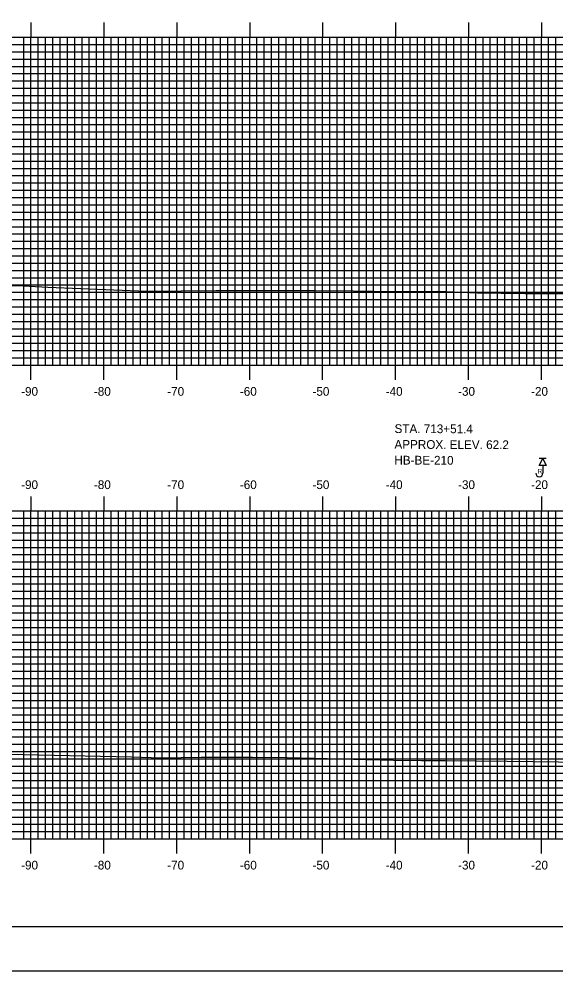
# Model space of a CAD drawing. Extents: x 855690 to 856034, y 364366 to 364586.
# Drawn here: x 855764.6 to 855838.3, y 364365.7 to 364496.3 of the extents above; entities that cross this region are included whole.
import ezdxf

# ---------------------------------------------------------------- set-up
doc = ezdxf.new("R2010")
doc.units = 0
for name, color, linetype in [('BORDER', 7, 'Continuous'), ('BORING - REFUSAL', 7, 'Continuous'), ('H_V ANNOTATION', 7, 'Continuous'), ('MAJOR', 7, 'Continuous'), ('MINOR', 7, 'Continuous'), ('PLOT BOUNDARY', 7, 'Continuous'), ('S_Roadway_Centerline', 7, 'Continuous')]:
    doc.layers.add(name, color=color, linetype=linetype)

msp = doc.modelspace()

# ---------------------------------------------------------------- linework, layer by layer
at = {"layer": 'BORDER'}
msp.add_lwpolyline([(855706.68, 364371.79), (856026.68, 364371.79), (856026.68, 364581.79), (855706.68, 364581.79)], close=True, dxfattribs=at)
at = {"layer": 'BORING - REFUSAL'}
for p, q in [((855836.96, 364435.99), (855836, 364435.99)), ((855836.48, 364435.03), (855836.48, 364433.97))]:
    msp.add_line(p, q, dxfattribs=at)
msp.add_lwpolyline([(855836.48, 364435.99), (855836.96, 364435.03), (855836, 364435.03)], close=True, dxfattribs=at)
msp.add_arc((855836, 364433.97), 0.485, 180, 0, dxfattribs=at)
at = {"layer": 'MAJOR'}
for p, q in [((855766.28, 364495.79), (855766.28, 364493.79)), ((855776.28, 364495.79), (855776.28, 364493.79)), ((855786.28, 364495.79), (855786.28, 364493.79)), ((855796.28, 364495.79), (855796.28, 364493.79)), ((855806.28, 364495.79), (855806.28, 364493.79)), ((855816.28, 364495.79), (855816.28, 364493.79)), ((855826.28, 364495.79), (855826.28, 364493.79)), ((855836.28, 364495.79), (855836.28, 364493.79)), ((855716.28, 364493.79), (855996.28, 364493.79)), ((855716.28, 364493.79), (855996.28, 364493.79)), ((855766.28, 364448.79), (855766.28, 364493.79)), ((855776.28, 364448.79), (855776.28, 364493.79)), ((855786.28, 364448.79), (855786.28, 364493.79)), ((855796.28, 364448.79), (855796.28, 364493.79)), ((855806.28, 364448.79), (855806.28, 364493.79)), ((855816.28, 364448.79), (855816.28, 364493.79)), ((855826.28, 364448.79), (855826.28, 364493.79)), ((855836.28, 364448.79), (855836.28, 364493.79)), ((855716.28, 364488.79), (855996.28, 364488.79)), ((855716.28, 364483.79), (855996.28, 364483.79)), ((855716.28, 364478.79), (855996.28, 364478.79)), ((855716.28, 364473.79), (855996.28, 364473.79)), ((855716.28, 364468.79), (855996.28, 364468.79)), ((855716.28, 364463.79), (855996.28, 364463.79)), ((855716.28, 364458.79), (855996.28, 364458.79)), ((855716.28, 364453.79), (855996.28, 364453.79)), ((855716.28, 364448.79), (855996.28, 364448.79)), ((855716.28, 364448.79), (855996.28, 364448.79)), ((855766.28, 364446.78), (855766.28, 364448.79)), ((855776.28, 364446.78), (855776.28, 364448.79)), ((855786.28, 364446.78), (855786.28, 364448.79)), ((855796.28, 364446.78), (855796.28, 364448.79)), ((855806.28, 364446.78), (855806.28, 364448.79)), ((855816.28, 364446.78), (855816.28, 364448.79)), ((855826.28, 364446.78), (855826.28, 364448.79)), ((855836.28, 364446.78), (855836.28, 364448.79)), ((855766.28, 364430.79), (855766.28, 364428.79)), ((855776.28, 364430.79), (855776.28, 364428.79)), ((855786.28, 364430.79), (855786.28, 364428.79)), ((855796.28, 364430.79), (855796.28, 364428.79)), ((855806.28, 364430.79), (855806.28, 364428.79)), ((855816.28, 364430.79), (855816.28, 364428.79)), ((855826.28, 364430.79), (855826.28, 364428.79)), ((855836.28, 364430.79), (855836.28, 364428.79)), ((855716.28, 364428.79), (855996.28, 364428.79)), ((855716.28, 364428.79), (855996.28, 364428.79)), ((855766.28, 364383.79), (855766.28, 364428.79)), ((855776.28, 364383.79), (855776.28, 364428.79)), ((855786.28, 364383.79), (855786.28, 364428.79)), ((855796.28, 364383.79), (855796.28, 364428.79)), ((855806.28, 364383.79), (855806.28, 364428.79)), ((855816.28, 364383.79), (855816.28, 364428.79)), ((855826.28, 364383.79), (855826.28, 364428.79)), ((855836.28, 364383.79), (855836.28, 364428.79)), ((855716.28, 364423.79), (855996.28, 364423.79)), ((855716.28, 364418.79), (855996.28, 364418.79)), ((855716.28, 364413.79), (855996.28, 364413.79)), ((855716.28, 364408.79), (855996.28, 364408.79)), ((855716.28, 364403.79), (855996.28, 364403.79)), ((855716.28, 364398.79), (855996.28, 364398.79)), ((855716.28, 364393.79), (855996.28, 364393.79)), ((855716.28, 364388.79), (855996.28, 364388.79)), ((855716.28, 364383.79), (855996.28, 364383.79)), ((855716.28, 364383.79), (855996.28, 364383.79)), ((855766.28, 364381.78), (855766.28, 364383.79)), ((855776.28, 364381.78), (855776.28, 364383.79)), ((855786.28, 364381.78), (855786.28, 364383.79)), ((855796.28, 364381.78), (855796.28, 364383.79)), ((855806.28, 364381.78), (855806.28, 364383.79)), ((855816.28, 364381.78), (855816.28, 364383.79)), ((855826.28, 364381.78), (855826.28, 364383.79)), ((855836.28, 364381.78), (855836.28, 364383.79))]:
    msp.add_line(p, q, dxfattribs=at)
at = {"layer": 'MINOR'}
for p, q in [((855765.28, 364448.79), (855765.28, 364493.79)), ((855767.28, 364448.79), (855767.28, 364493.79)), ((855768.28, 364448.79), (855768.28, 364493.79)), ((855769.28, 364448.79), (855769.28, 364493.79)), ((855770.28, 364448.79), (855770.28, 364493.79)), ((855771.28, 364448.79), (855771.28, 364493.79)), ((855772.28, 364448.79), (855772.28, 364493.79)), ((855773.28, 364448.79), (855773.28, 364493.79)), ((855774.28, 364448.79), (855774.28, 364493.79)), ((855775.28, 364448.79), (855775.28, 364493.79)), ((855777.28, 364448.79), (855777.28, 364493.79)), ((855778.28, 364448.79), (855778.28, 364493.79)), ((855779.28, 364448.79), (855779.28, 364493.79)), ((855780.28, 364448.79), (855780.28, 364493.79)), ((855781.28, 364448.79), (855781.28, 364493.79)), ((855782.28, 364448.79), (855782.28, 364493.79)), ((855783.28, 364448.79), (855783.28, 364493.79)), ((855784.28, 364448.79), (855784.28, 364493.79)), ((855785.28, 364448.79), (855785.28, 364493.79)), ((855787.28, 364448.79), (855787.28, 364493.79)), ((855788.28, 364448.79), (855788.28, 364493.79)), ((855789.28, 364448.79), (855789.28, 364493.79)), ((855790.28, 364448.79), (855790.28, 364493.79)), ((855791.28, 364448.79), (855791.28, 364493.79)), ((855792.28, 364448.79), (855792.28, 364493.79)), ((855793.28, 364448.79), (855793.28, 364493.79)), ((855794.28, 364448.79), (855794.28, 364493.79)), ((855795.28, 364448.79), (855795.28, 364493.79)), ((855797.28, 364448.79), (855797.28, 364493.79)), ((855798.28, 364448.79), (855798.28, 364493.79)), ((855799.28, 364448.79), (855799.28, 364493.79)), ((855800.28, 364448.79), (855800.28, 364493.79)), ((855801.28, 364448.79), (855801.28, 364493.79)), ((855802.28, 364448.79), (855802.28, 364493.79)), ((855803.28, 364448.79), (855803.28, 364493.79)), ((855804.28, 364448.79), (855804.28, 364493.79)), ((855805.28, 364448.79), (855805.28, 364493.79)), ((855807.28, 364448.79), (855807.28, 364493.79)), ((855808.28, 364448.79), (855808.28, 364493.79)), ((855809.28, 364448.79), (855809.28, 364493.79)), ((855810.28, 364448.79), (855810.28, 364493.79)), ((855811.28, 364448.79), (855811.28, 364493.79)), ((855812.28, 364448.79), (855812.28, 364493.79)), ((855813.28, 364448.79), (855813.28, 364493.79)), ((855814.28, 364448.79), (855814.28, 364493.79)), ((855815.28, 364448.79), (855815.28, 364493.79)), ((855817.28, 364448.79), (855817.28, 364493.79)), ((855818.28, 364448.79), (855818.28, 364493.79)), ((855819.28, 364448.79), (855819.28, 364493.79)), ((855820.28, 364448.79), (855820.28, 364493.79)), ((855821.28, 364448.79), (855821.28, 364493.79)), ((855822.28, 364448.79), (855822.28, 364493.79)), ((855823.28, 364448.79), (855823.28, 364493.79)), ((855824.28, 364448.79), (855824.28, 364493.79)), ((855825.28, 364448.79), (855825.28, 364493.79)), ((855827.28, 364448.79), (855827.28, 364493.79)), ((855828.28, 364448.79), (855828.28, 364493.79)), ((855829.28, 364448.79), (855829.28, 364493.79)), ((855830.28, 364448.79), (855830.28, 364493.79)), ((855831.28, 364448.79), (855831.28, 364493.79)), ((855832.28, 364448.79), (855832.28, 364493.79)), ((855833.28, 364448.79), (855833.28, 364493.79)), ((855834.28, 364448.79), (855834.28, 364493.79)), ((855835.28, 364448.79), (855835.28, 364493.79)), ((855837.28, 364448.79), (855837.28, 364493.79)), ((855838.28, 364448.79), (855838.28, 364493.79)), ((855716.28, 364492.79), (855996.28, 364492.79)), ((855716.28, 364491.79), (855996.28, 364491.79)), ((855716.28, 364490.79), (855996.28, 364490.79)), ((855716.28, 364489.79), (855996.28, 364489.79)), ((855716.28, 364487.79), (855996.28, 364487.79)), ((855716.28, 364486.79), (855996.28, 364486.79)), ((855716.28, 364485.79), (855996.28, 364485.79)), ((855716.28, 364484.79), (855996.28, 364484.79)), ((855716.28, 364482.79), (855996.28, 364482.79)), ((855716.28, 364481.79), (855996.28, 364481.79)), ((855716.28, 364480.79), (855996.28, 364480.79)), ((855716.28, 364479.79), (855996.28, 364479.79)), ((855716.28, 364477.79), (855996.28, 364477.79)), ((855716.28, 364476.79), (855996.28, 364476.79)), ((855716.28, 364475.79), (855996.28, 364475.79)), ((855716.28, 364474.79), (855996.28, 364474.79)), ((855716.28, 364472.79), (855996.28, 364472.79)), ((855716.28, 364471.79), (855996.28, 364471.79)), ((855716.28, 364470.79), (855996.28, 364470.79)), ((855716.28, 364469.79), (855996.28, 364469.79)), ((855716.28, 364467.79), (855996.28, 364467.79)), ((855716.28, 364466.79), (855996.28, 364466.79)), ((855716.28, 364465.79), (855996.28, 364465.79)), ((855716.28, 364464.79), (855996.28, 364464.79)), ((855716.28, 364462.79), (855996.28, 364462.79)), ((855716.28, 364461.79), (855996.28, 364461.79)), ((855716.28, 364460.79), (855996.28, 364460.79)), ((855716.28, 364459.79), (855996.28, 364459.79)), ((855716.28, 364457.79), (855996.28, 364457.79)), ((855716.28, 364456.79), (855996.28, 364456.79)), ((855716.28, 364455.79), (855996.28, 364455.79)), ((855716.28, 364454.79), (855996.28, 364454.79)), ((855716.28, 364452.79), (855996.28, 364452.79)), ((855716.28, 364451.79), (855996.28, 364451.79)), ((855716.28, 364450.79), (855996.28, 364450.79)), ((855716.28, 364449.79), (855996.28, 364449.79)), ((855716.28, 364427.79), (855996.28, 364427.79)), ((855765.28, 364383.79), (855765.28, 364428.79)), ((855767.28, 364383.79), (855767.28, 364428.79)), ((855768.28, 364383.79), (855768.28, 364428.79)), ((855769.28, 364383.79), (855769.28, 364428.79)), ((855770.28, 364383.79), (855770.28, 364428.79)), ((855771.28, 364383.79), (855771.28, 364428.79)), ((855772.28, 364383.79), (855772.28, 364428.79)), ((855773.28, 364383.79), (855773.28, 364428.79)), ((855774.28, 364383.79), (855774.28, 364428.79)), ((855775.28, 364383.79), (855775.28, 364428.79)), ((855777.28, 364383.79), (855777.28, 364428.79)), ((855778.28, 364383.79), (855778.28, 364428.79)), ((855779.28, 364383.79), (855779.28, 364428.79)), ((855780.28, 364383.79), (855780.28, 364428.79)), ((855781.28, 364383.79), (855781.28, 364428.79)), ((855782.28, 364383.79), (855782.28, 364428.79)), ((855783.28, 364383.79), (855783.28, 364428.79)), ((855784.28, 364383.79), (855784.28, 364428.79)), ((855785.28, 364383.79), (855785.28, 364428.79)), ((855787.28, 364383.79), (855787.28, 364428.79)), ((855788.28, 364383.79), (855788.28, 364428.79)), ((855789.28, 364383.79), (855789.28, 364428.79)), ((855790.28, 364383.79), (855790.28, 364428.79)), ((855791.28, 364383.79), (855791.28, 364428.79)), ((855792.28, 364383.79), (855792.28, 364428.79)), ((855793.28, 364383.79), (855793.28, 364428.79)), ((855794.28, 364383.79), (855794.28, 364428.79)), ((855795.28, 364383.79), (855795.28, 364428.79)), ((855797.28, 364383.79), (855797.28, 364428.79)), ((855798.28, 364383.79), (855798.28, 364428.79)), ((855799.28, 364383.79), (855799.28, 364428.79)), ((855800.28, 364383.79), (855800.28, 364428.79)), ((855801.28, 364383.79), (855801.28, 364428.79)), ((855802.28, 364383.79), (855802.28, 364428.79)), ((855803.28, 364383.79), (855803.28, 364428.79)), ((855804.28, 364383.79), (855804.28, 364428.79)), ((855805.28, 364383.79), (855805.28, 364428.79)), ((855807.28, 364383.79), (855807.28, 364428.79)), ((855808.28, 364383.79), (855808.28, 364428.79)), ((855809.28, 364383.79), (855809.28, 364428.79)), ((855810.28, 364383.79), (855810.28, 364428.79)), ((855811.28, 364383.79), (855811.28, 364428.79)), ((855812.28, 364383.79), (855812.28, 364428.79)), ((855813.28, 364383.79), (855813.28, 364428.79)), ((855814.28, 364383.79), (855814.28, 364428.79)), ((855815.28, 364383.79), (855815.28, 364428.79)), ((855817.28, 364383.79), (855817.28, 364428.79)), ((855818.28, 364383.79), (855818.28, 364428.79)), ((855819.28, 364383.79), (855819.28, 364428.79)), ((855820.28, 364383.79), (855820.28, 364428.79)), ((855821.28, 364383.79), (855821.28, 364428.79)), ((855822.28, 364383.79), (855822.28, 364428.79)), ((855823.28, 364383.79), (855823.28, 364428.79)), ((855824.28, 364383.79), (855824.28, 364428.79)), ((855825.28, 364383.79), (855825.28, 364428.79)), ((855827.28, 364383.79), (855827.28, 364428.79)), ((855828.28, 364383.79), (855828.28, 364428.79)), ((855829.28, 364383.79), (855829.28, 364428.79)), ((855830.28, 364383.79), (855830.28, 364428.79)), ((855831.28, 364383.79), (855831.28, 364428.79)), ((855832.28, 364383.79), (855832.28, 364428.79)), ((855833.28, 364383.79), (855833.28, 364428.79)), ((855834.28, 364383.79), (855834.28, 364428.79)), ((855835.28, 364383.79), (855835.28, 364428.79)), ((855837.28, 364383.79), (855837.28, 364428.79)), ((855838.28, 364383.79), (855838.28, 364428.79)), ((855716.28, 364426.79), (855996.28, 364426.79)), ((855716.28, 364425.79), (855996.28, 364425.79)), ((855716.28, 364424.79), (855996.28, 364424.79)), ((855716.28, 364422.79), (855996.28, 364422.79)), ((855716.28, 364421.79), (855996.28, 364421.79)), ((855716.28, 364420.79), (855996.28, 364420.79)), ((855716.28, 364419.79), (855996.28, 364419.79)), ((855716.28, 364417.79), (855996.28, 364417.79)), ((855716.28, 364416.79), (855996.28, 364416.79)), ((855716.28, 364415.79), (855996.28, 364415.79)), ((855716.28, 364414.79), (855996.28, 364414.79)), ((855716.28, 364412.79), (855996.28, 364412.79)), ((855716.28, 364411.79), (855996.28, 364411.79)), ((855716.28, 364410.79), (855996.28, 364410.79)), ((855716.28, 364409.79), (855996.28, 364409.79)), ((855716.28, 364407.79), (855996.28, 364407.79)), ((855716.28, 364406.79), (855996.28, 364406.79)), ((855716.28, 364405.79), (855996.28, 364405.79)), ((855716.28, 364404.79), (855996.28, 364404.79)), ((855716.28, 364402.79), (855996.28, 364402.79)), ((855716.28, 364401.79), (855996.28, 364401.79)), ((855716.28, 364400.79), (855996.28, 364400.79)), ((855716.28, 364399.79), (855996.28, 364399.79)), ((855716.28, 364397.79), (855996.28, 364397.79)), ((855716.28, 364396.79), (855996.28, 364396.79)), ((855716.28, 364395.79), (855996.28, 364395.79)), ((855716.28, 364394.79), (855996.28, 364394.79)), ((855716.28, 364392.79), (855996.28, 364392.79)), ((855716.28, 364391.79), (855996.28, 364391.79)), ((855716.28, 364390.79), (855996.28, 364390.79)), ((855716.28, 364389.79), (855996.28, 364389.79)), ((855716.28, 364387.79), (855996.28, 364387.79)), ((855716.28, 364386.79), (855996.28, 364386.79)), ((855716.28, 364385.79), (855996.28, 364385.79)), ((855716.28, 364384.79), (855996.28, 364384.79))]:
    msp.add_line(p, q, dxfattribs=at)
at = {"layer": 'PLOT BOUNDARY'}
msp.add_lwpolyline([(855690.5, 364365.67), (856030.5, 364365.67), (856030.5, 364585.67), (855690.5, 364585.67)], close=True, dxfattribs=at)
at = {"layer": 'S_Roadway_Centerline'}
for points in [[(855716.28, 364459.71), (855721.54, 364459.71), (855736.38, 364459.78), (855740.54, 364459.68), (855745.4, 364459.58), (855764.38, 364459.71), (855768.57, 364459.49), (855782.16, 364458.94), (855786.89, 364459), (855791.64, 364459.04), (855805.12, 364459.05), (855810.51, 364459), (855816.17, 364458.91), (855822.08, 364458.96), (855827.51, 364458.73), (855834.03, 364458.61), (855840.8, 364458.61)], [(855716.28, 364396.58), (855718.3, 364396.5), (855737.2, 364395.84), (855738.26, 364395.83), (855743.8, 364395.75), (855760.2, 364395.47), (855763.11, 364395.42), (855780.07, 364395.03), (855784.13, 364394.9), (855789.62, 364395.01), (855796.66, 364395.01), (855801.4, 364394.98), (855815.99, 364394.6), (855819.85, 364394.55), (855823.07, 364394.55), (855831.57, 364394.47), (855842.14, 364394.32)]]:
    msp.add_lwpolyline(points, dxfattribs=at)

# ---------------------------------------------------------------- texts
at = {"layer": 'BORING - REFUSAL'}
for s, p in [('STA. 713+51.4', (855816.14, 364439.48)), ('APPROX. ELEV. 62.2', (855816.13, 364437.32)), ('HB-BE-210', (855816.12, 364435.16))]:
    msp.add_text(s, height=1.2, rotation=359.8142, dxfattribs=at).set_placement(p)
msp.add_text('R', height=0.64, dxfattribs=at).set_placement((855835.77, 364433.91))
at = {"layer": 'H_V ANNOTATION'}
for s, p in [('-90', (855764.93, 364444.59)), ('-80', (855774.91, 364444.59)), ('-70', (855784.97, 364444.59)), ('-60', (855794.93, 364444.59)), ('-50', (855804.89, 364444.59)), ('-40', (855814.93, 364444.59)), ('-30', (855824.86, 364444.59)), ('-20', (855834.87, 364444.59)), ('-90', (855764.93, 364431.79)), ('-80', (855774.91, 364431.79)), ('-70', (855784.97, 364431.79)), ('-60', (855794.93, 364431.79)), ('-50', (855804.89, 364431.79)), ('-40', (855814.93, 364431.79)), ('-30', (855824.86, 364431.79)), ('-20', (855834.87, 364431.79)), ('-90', (855764.93, 364379.59)), ('-80', (855774.91, 364379.59)), ('-70', (855784.97, 364379.59)), ('-60', (855794.93, 364379.59)), ('-50', (855804.89, 364379.59)), ('-40', (855814.93, 364379.59)), ('-30', (855824.86, 364379.59)), ('-20', (855834.87, 364379.59))]:
    msp.add_text(s, height=1.2, dxfattribs=at).set_placement(p)

doc.saveas('drawing.dxf')
